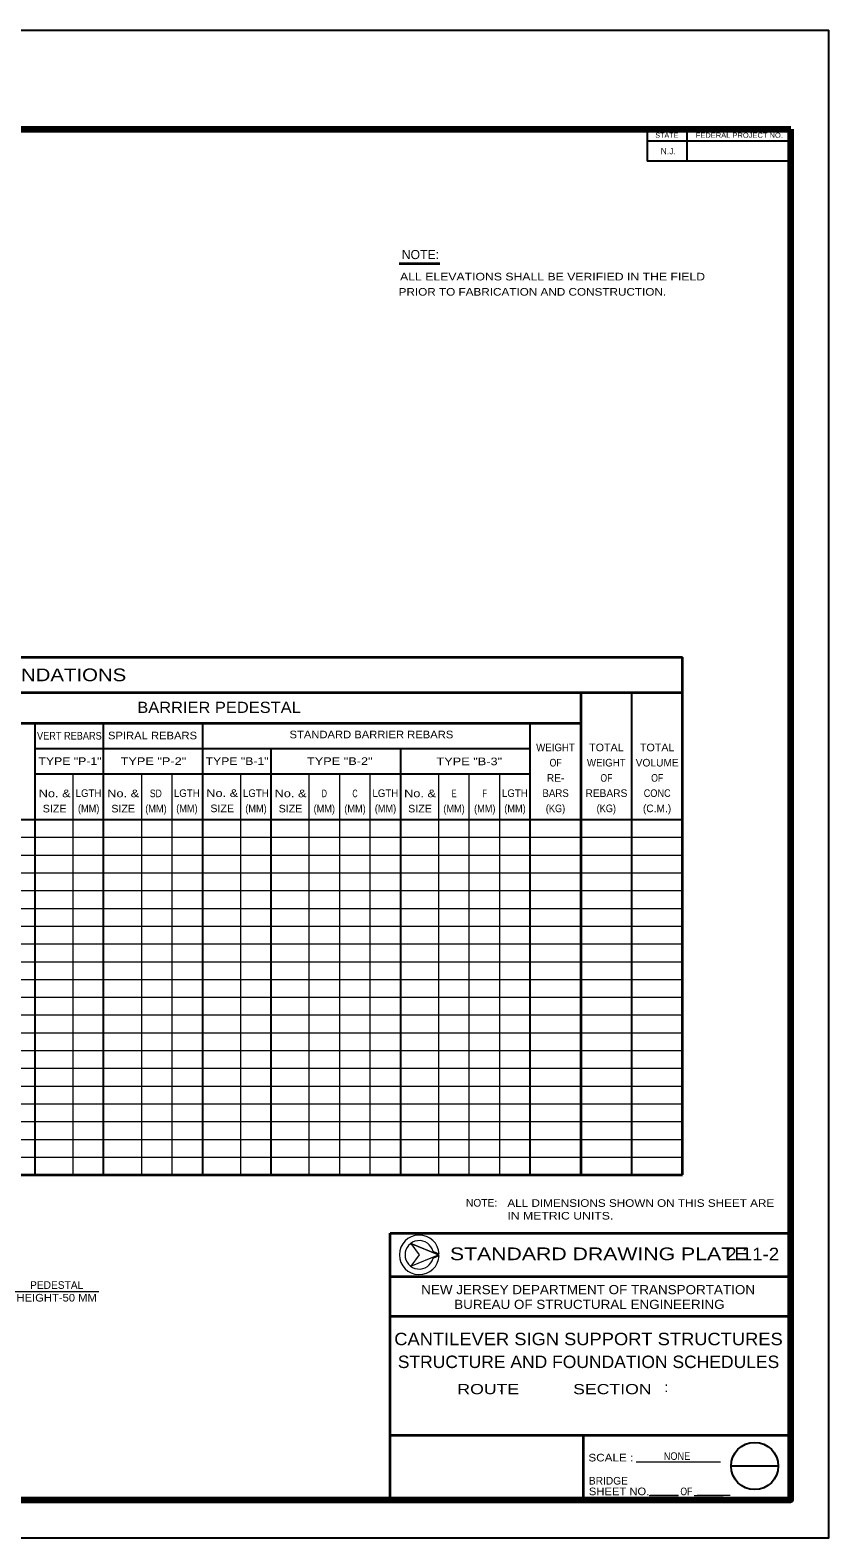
# Model space of a CAD drawing. Extents: x 312601.858 to 312602.699, y 144420.109 to 144420.704.
# Drawn here: x 312602.384 to 312602.699, y 144420.109 to 144420.704 of the extents above; entities that cross this region are included whole.
import ezdxf
from ezdxf.enums import TextEntityAlignment as Align

# ---------------------------------------------------------------- set-up
doc = ezdxf.new("R2010")
doc.units = 0
doc.header["$LTSCALE"] = 0.0012
for name, color, linetype, lineweight in [('1', 7, 'Continuous', 13), ('2', 7, 'Continuous', 13), ('39', 7, 'Continuous', 13), ('61', 7, 'Continuous', 25)]:
    doc.layers.add(name, color=color, linetype=linetype, lineweight=lineweight)
doc.layers.add('4', color=7, linetype='Continuous')

msp = doc.modelspace()

# ---------------------------------------------------------------- linework, layer by layer
at = {"layer": '1', "lineweight": 35}
for p, q in [((312602.159, 144420.4565), (312602.6412, 144420.4565)), ((312602.6412, 144420.2525), (312602.6412, 144420.4565)), ((312602.159, 144420.4425), (312602.6412, 144420.4425)), ((312602.6012, 144420.2525), (312602.6012, 144420.4425)), ((312602.1584, 144420.4305), (312602.6008, 144420.4305)), ((312602.1584, 144420.2525), (312602.6412, 144420.2525))]:
    msp.add_line(p, q, dxfattribs=at)
at = {"layer": '1', "lineweight": 25}
for p, q in [((312602.6212, 144420.2525), (312602.6212, 144420.4425)), ((312602.3862, 144420.2525), (312602.3862, 144420.4305)), ((312602.4132, 144420.2525), (312602.4132, 144420.4305)), ((312602.4522, 144420.2525), (312602.4522, 144420.4305)), ((312602.5812, 144420.2525), (312602.5812, 144420.4305)), ((312602.3862, 144420.4205), (312602.5812, 144420.4205)), ((312602.4792, 144420.2525), (312602.4792, 144420.4205)), ((312602.5302, 144420.2525), (312602.5302, 144420.4205)), ((312602.3862, 144420.4105), (312602.5812, 144420.4105)), ((312602.1584, 144420.3925), (312602.6412, 144420.3925))]:
    msp.add_line(p, q, dxfattribs=at)
at = {"layer": '1'}
for p, q in [((312602.3891, 144420.4205), (312602.5722, 144420.4205)), ((312602.4012, 144420.2525), (312602.4012, 144420.4105)), ((312602.4012, 144420.2525), (312602.4012, 144420.4105)), ((312602.4282, 144420.2525), (312602.4282, 144420.4105)), ((312602.4402, 144420.2525), (312602.4402, 144420.4105)), ((312602.4672, 144420.2525), (312602.4672, 144420.4105)), ((312602.4942, 144420.2525), (312602.4942, 144420.4105)), ((312602.5062, 144420.2525), (312602.5062, 144420.4101)), ((312602.5182, 144420.2525), (312602.5182, 144420.4105)), ((312602.5452, 144420.2525), (312602.5452, 144420.4105)), ((312602.5572, 144420.2525), (312602.5572, 144420.4105)), ((312602.5692, 144420.2525), (312602.5692, 144420.4105)), ((312602.1584, 144420.3855), (312602.6412, 144420.3855)), ((312602.1584, 144420.3785), (312602.6412, 144420.3785)), ((312602.1584, 144420.3715), (312602.6412, 144420.3715)), ((312602.1584, 144420.3645), (312602.6412, 144420.3645)), ((312602.1584, 144420.3575), (312602.6412, 144420.3575)), ((312602.1584, 144420.3505), (312602.6412, 144420.3505)), ((312602.1584, 144420.3435), (312602.6412, 144420.3435)), ((312602.1584, 144420.3365), (312602.6412, 144420.3365)), ((312602.1584, 144420.3295), (312602.6412, 144420.3295)), ((312602.1584, 144420.3225), (312602.6412, 144420.3225)), ((312602.1584, 144420.3155), (312602.6412, 144420.3155)), ((312601.9375, 144420.3085), (312602.6412, 144420.3085)), ((312602.1584, 144420.3015), (312602.6412, 144420.3015)), ((312602.1584, 144420.2945), (312602.6412, 144420.2945)), ((312602.1584, 144420.2875), (312602.6412, 144420.2875)), ((312602.1584, 144420.2805), (312602.6412, 144420.2805)), ((312602.1584, 144420.2735), (312602.6412, 144420.2735)), ((312602.1584, 144420.2665), (312602.6412, 144420.2665)), ((312602.1584, 144420.2595), (312602.6412, 144420.2595)), ((312602.543, 144420.2197), (312602.5453, 144420.2207)), ((312602.3754, 144420.2066), (312602.4113, 144420.2066))]:
    msp.add_line(p, q, dxfattribs=at)
for points in [[(312602.5451, 144420.221), (312602.5342, 144420.2255), (312602.5451, 144420.221)], [(312602.5453, 144420.2213), (312602.543, 144420.2223), (312602.5429, 144420.2223)]]:
    msp.add_lwpolyline(points, dxfattribs=at)
for points in [[(312602.5451, 144420.221), (312602.5342, 144420.2255), (312602.5374, 144420.221), (312602.5342, 144420.2165)], [(312602.5374, 144420.221), (312602.5342, 144420.2165), (312602.5451, 144420.221), (312602.5342, 144420.2255)]]:
    msp.add_lwpolyline(points, close=True, dxfattribs=at)
for radius, start, end in [(0.0078, 2.21392, 357.78608), (0.0056, 13.69411, 346.30589)]:
    msp.add_arc((312602.5375, 144420.221), radius, start, end, dxfattribs=at)
at = {"layer": '2', "lineweight": 35}
msp.add_line((312602.5296, 144420.6116), (312602.5456, 144420.6116), dxfattribs=at)
at = {"layer": '2'}
for p, q in [((312602.6281, 144420.1262), (312602.6396, 144420.1262)), ((312602.6457, 144420.1262), (312602.6572, 144420.1262))]:
    msp.add_line(p, q, dxfattribs=at)
at = {"layer": '39', "lineweight": 25}
for p, q in [((312601.8578, 144420.7035), (312602.6988, 144420.7035)), ((312602.5735, 144420.6645), (312602.6838, 144420.6645)), ((312602.6838, 144420.6514), (312602.6838, 144420.6645)), ((312602.6789, 144420.1378), (312602.6603, 144420.1378)), ((312602.452, 144420.1245), (312602.6838, 144420.1245))]:
    msp.add_line(p, q, dxfattribs=at)
at = {"layer": '39', "lineweight": 35}
for p, q in [((312602.526, 144420.1245), (312602.526, 144420.2295)), ((312602.526, 144420.2295), (312602.6838, 144420.2295)), ((312602.6838, 144420.2295), (312602.6838, 144420.1245)), ((312602.526, 144420.2124), (312602.6838, 144420.2124)), ((312602.526, 144420.1968), (312602.6838, 144420.1968)), ((312602.526, 144420.1499), (312602.6838, 144420.1499)), ((312602.6022, 144420.1248), (312602.6022, 144420.1499))]:
    msp.add_line(p, q, dxfattribs=at)
at = {"layer": '39'}
for p, q in [((312602.6022, 144420.1499), (312602.6838, 144420.1499)), ((312602.6022, 144420.1248), (312602.6022, 144420.1499)), ((312602.6022, 144420.1248), (312602.6022, 144420.1499)), ((312602.6229, 144420.1395), (312602.6561, 144420.1395)), ((312602.6284, 144420.1263), (312602.6394, 144420.1263)), ((312602.6469, 144420.1263), (312602.66, 144420.1263))]:
    msp.add_line(p, q, dxfattribs=at)
at = {"layer": '39', "lineweight": 25}
msp.add_lwpolyline([(312601.8578, 144420.1095), (312602.6988, 144420.1095), (312602.6988, 144420.7035)], dxfattribs=at)
at = {"layer": '39', "lineweight": 158}
for points in [[(312601.9088, 144420.1245), (312602.6838, 144420.1245), (312602.6838, 144420.6645)], [(312601.9088, 144420.1247), (312601.9088, 144420.6645), (312602.6838, 144420.6645)]]:
    msp.add_lwpolyline(points, dxfattribs=at)
at = {"layer": '39'}
msp.add_lwpolyline([(312602.5451, 144420.221), (312602.5342, 144420.2255), (312602.5374, 144420.221), (312602.5342, 144420.2165)], close=True, dxfattribs=at)
at = {"layer": '39', "lineweight": 25}
msp.add_circle((312602.6696, 144420.1378), 0.0093, dxfattribs=at)
at = {"layer": '61'}
for p, q in [((312602.6273, 144420.6645), (312602.6273, 144420.6519)), ((312602.6429, 144420.6645), (312602.6429, 144420.6519)), ((312602.6838, 144420.6597), (312602.6273, 144420.6597)), ((312602.6838, 144420.6519), (312602.6273, 144420.6519))]:
    msp.add_line(p, q, dxfattribs=at)

# ---------------------------------------------------------------- texts
at = {"layer": '1'}
msp.add_text('PEDESTAL', height=0.003, dxfattribs=at).set_placement((312602.3947, 144420.2076), align=Align.CENTER)
at = {"layer": '1', "width": 1.1}
msp.add_text('HEIGHT-50 MM', height=0.003, dxfattribs=at).set_placement((312602.3947, 144420.2026), align=Align.CENTER)
at = {"layer": '2'}
for s, height, p in [('NOTE:', 0.0036, (312602.53795, 144420.6133)), ('VOLUME', 0.003, (312602.6312, 144420.4134)), ('RE-', 0.003, (312602.5912, 144420.4074)), ('REBARS', 0.003, (312602.6112, 144420.4014)), ('(C.M.)', 0.003, (312602.63115, 144420.3954))]:
    msp.add_text(s, height=height, dxfattribs=at).set_placement(p, align=Align.CENTER)
for s, height, width, p in [('ALL ELEVATIONS SHALL BE VERIFIED IN THE FIELD', 0.003, 1.2, (312602.59, 144420.6049)), ('PRIOR TO FABRICATION AND CONSTRUCTION.', 0.003, 1.15, (312602.58205, 144420.5989)), ('CANTILEVER  SIGN  SUPPORTS  -  SCHEDULE  OF  FOUNDATIONS', 0.005, 1.2, (312602.2937, 144420.447)), ('BARRIER PEDESTAL', 0.0044, 1.1, (312602.45865, 144420.4345)), ('VERT REBARS', 0.003, 0.9, (312602.3997, 144420.424)), ('SPIRAL REBARS', 0.003, 1.1, (312602.43245, 144420.4241)), ('STANDARD BARRIER REBARS', 0.003, 1.1, (312602.51865, 144420.4245)), ('WEIGHT', 0.003, 0.95, (312602.59115, 144420.4194)), ('TOTAL', 0.003, 1.05, (312602.6112, 144420.4194)), ('TOTAL', 0.003, 1.05, (312602.6312, 144420.4194)), ('TYPE "P-1"', 0.003, 1.2, (312602.39995, 144420.414)), ('TYPE "P-2"', 0.003, 1.25, (312602.4328, 144420.414)), ('TYPE "B-1"', 0.003, 1.2, (312602.46575, 144420.414)), ('TYPE "B-2"', 0.003, 1.25, (312602.5062, 144420.414)), ('TYPE "B-3"', 0.003, 1.25, (312602.5572, 144420.4139)), ('OF', 0.003, 0.85, (312602.5912, 144420.4134)), ('WEIGHT', 0.003, 0.95, (312602.61115, 144420.4134)), ('OF', 0.003, 0.85, (312602.6112, 144420.4074)), ('OF', 0.003, 0.85, (312602.6312, 144420.4074)), ('No. &', 0.003, 1.25, (312602.3939, 144420.4013)), ('LGTH', 0.003, 0.95, (312602.40725, 144420.4014)), ('No. &', 0.003, 1.25, (312602.4209, 144420.4013)), ('SD', 0.003, 0.85, (312602.43375, 144420.4013)), ('LGTH', 0.003, 0.95, (312602.44595, 144420.4014)), ('No. &', 0.003, 1.25, (312602.4599, 144420.4014)), ('LGTH', 0.003, 0.95, (312602.47315, 144420.4014)), ('No. &', 0.003, 1.25, (312602.4868, 144420.4013)), ('D', 0.003, 0.6, (312602.5001, 144420.4013)), ('C', 0.003, 0.6, (312602.5122, 144420.4013)), ('LGTH', 0.003, 0.95, (312602.52415, 144420.4014)), ('No. &', 0.003, 1.25, (312602.5378, 144420.4013)), ('E', 0.003, 0.7, (312602.5512, 144420.4013)), ('F', 0.003, 0.7, (312602.56325, 144420.4013)), ('LGTH', 0.003, 0.95, (312602.57515, 144420.4014)), ('BARS', 0.003, 0.95, (312602.5912, 144420.4014)), ('CONC', 0.003, 0.9, (312602.6312, 144420.4014)), ('SIZE', 0.003, 1.05, (312602.3939, 144420.3953)), ('(MM)', 0.003, 0.9, (312602.4073, 144420.3954)), ('SIZE', 0.003, 1.05, (312602.4209, 144420.3953)), ('(MM)', 0.003, 0.9, (312602.4338, 144420.3953)), ('(MM)', 0.003, 0.9, (312602.446, 144420.3954)), ('SIZE', 0.003, 1.05, (312602.4599, 144420.3954)), ('(MM)', 0.003, 0.9, (312602.4732, 144420.3954)), ('SIZE', 0.003, 1.05, (312602.4868, 144420.3953)), ('(MM)', 0.003, 0.9, (312602.5001, 144420.3953)), ('(MM)', 0.003, 0.9, (312602.5122, 144420.3953)), ('(MM)', 0.003, 0.9, (312602.5242, 144420.3954)), ('SIZE', 0.003, 1.05, (312602.5378, 144420.3953)), ('(MM)', 0.003, 0.9, (312602.5512, 144420.3953)), ('(MM)', 0.003, 0.9, (312602.5633, 144420.3953)), ('(MM)', 0.003, 0.9, (312602.5752, 144420.3954)), ('(KG)', 0.003, 0.9, (312602.59115, 144420.3954)), ('(KG)', 0.003, 0.9, (312602.61115, 144420.3954)), ('2.11-2', 0.005, 1.1, (312602.6688, 144420.2188)), ('CANTILEVER SIGN SUPPORT STRUCTURES', 0.0049, 1.1, (312602.60415, 144420.1854)), ('STRUCTURE AND FOUNDATION SCHEDULES', 0.0049, 1.05, (312602.60415, 144420.1764)), ('NONE', 0.003, 0.9, (312602.639, 144420.1402))]:
    msp.add_text(s, height=height, dxfattribs=dict(at, width=width)).set_placement(p, align=Align.CENTER)
at = {"layer": '39'}
for s, height, width, p in [('STANDARD DRAWING PLATE       ', 0.005, 1.25, (312602.61645, 144420.2189)), ('NEW JERSEY DEPARTMENT OF TRANSPORTATION', 0.003599, 1.1, (312602.604, 144420.2055)), ('BUREAU OF STRUCTURAL ENGINEERING', 0.0036, 1.1, (312602.6045, 144420.1997)), ('ROUTE           SECTION', 0.004, 1.3, (312602.59075, 144420.1661)), ('SCALE :', 0.003, 1.15, (312602.61295, 144420.1396)), ('OF', 0.003, 0.85, (312602.6427, 144420.1263))]:
    msp.add_text(s, height=height, dxfattribs=dict(at, width=width)).set_placement(p, align=Align.CENTER)
for p in [(312602.56974, 144420.1671), (312602.63484, 144420.1669)]:
    msp.add_text(':', height=0.004, dxfattribs=at).set_placement(p, align=Align.CENTER)
at = {"layer": '39', "width": 1.1}
msp.add_text('SHEET NO.', height=0.003, dxfattribs=at).set_placement((312602.6043, 144420.1263))
at = {"layer": '39'}
msp.add_text('BRIDGE', height=0.003, dxfattribs=at).set_placement((312602.6043, 144420.1305))
at = {"layer": '4'}
msp.add_text('NOTE:', height=0.003, dxfattribs=at).set_placement((312602.5559, 144420.24))
for s, width, p in [('ALL DIMENSIONS SHOWN ON THIS SHEET ARE', 1.15, (312602.5722, 144420.2399)), ('IN METRIC UNITS.', 1.2, (312602.5722, 144420.2349))]:
    msp.add_text(s, height=0.003, dxfattribs=dict(at, width=width)).set_placement(p)
at = {"layer": '61'}
for s, width, p in [('STATE', 1.05, (312602.635, 144420.6611)), ('FEDERAL PROJECT NO.', 1.1, (312602.66355, 144420.6611))]:
    msp.add_text(s, height=0.00201, dxfattribs=dict(at, width=width)).set_placement(p, align=Align.CENTER)
msp.add_text('N.J.', height=0.002512, dxfattribs=at).set_placement((312602.63555, 144420.6546), align=Align.CENTER)

doc.saveas('drawing.dxf')
